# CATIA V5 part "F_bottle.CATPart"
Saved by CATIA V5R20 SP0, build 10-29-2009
Part number: Part1
Material "DS star": density 1000 kg/m3
Bounding box of the stored display mesh (mm): x -47.5 to 47.5, y -47.5 to 47.5, z -150 to 95
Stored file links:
  C:\Users\Lenovo\Desktop\我所做的源文件catia\bottle.CATPart
  D:\CATIAR20\win_b64\startup\materials\Catalog.CATMaterial
  D:\CATIAR20\win_b64\startup\materials\DS_star.jpg
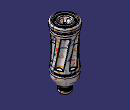
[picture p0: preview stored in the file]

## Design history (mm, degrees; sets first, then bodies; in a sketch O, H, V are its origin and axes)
Body1 (main body), material "DS star"
  Sketch1 on yz-plane, origin (0, 0, 0), H (0, 1, 0), V (0, 0, 1)
    point P1 (0, 70)
    line L1 (0, 70) -> (45, 70)
    line L2 (45, -70) -> (0, -70)
    line L3 (0, -70) -> (0, 70)
    point P2 (45, 70)
    point P3 (45, -70)
    arc A1 centre (532.5, 0) radius 492.5 from (45, 70) to (45, -70) ccw
    point P5 (532.5, 0)
    length L1 = 45
    distance P2 P3 = 140
    distance A1 L3 = 40
    coincidence: P1 V, P5 H
    horizontal: L1 H, L2 H
    vertical: L3 V
    symmetry: L1 L2 H
  Shaft1: profile Sketch1, axis Z axis, angle 360
  Sketch2 on face of Shaft1 from Sketch1.L1, origin (0, 0, 70), H (1, 0, 0), V (0, 1, 0)
    circle A1 centre (0, 0) radius 40
    radius A1 = 40
  Pad1: profile Sketch2, direction (0, 0, 1), length 5
  Sketch3 on end face of Pad1, origin (0, 0, 75), H (1, 0, 0), V (0, 1, 0)
    circle A1 centre (0, 0) radius 47.5
    radius A1 = 47.5
  Pad2: profile Sketch3, direction (0, 0, 1), length 20
  Fillet1: radius 4, on edge [face of Shaft1 from Sketch1.A1 | face of Shaft1 from Sketch1.L1]
  Fillet2: radius 6, on end face of Pad2; face of Pad2 from Sketch3.A1
  Fillet3: radius 2, on edge [face of Pad1 from Sketch2.A1 | start face of Pad2]; edge [face of Shaft1 from Sketch1.L1 | face of Pad1 from Sketch2.A1]
  Sketch4 on face of Shaft1 from Sketch1.L2, origin (0, 0, -70), H (1, 0, 0), V (0, -1, 0)
    circle A1 centre (0, 0) radius 40
    radius A1 = 40
  Pad3: profile Sketch4, direction (0, 0, -1), length 5
  Sketch5 on yz-plane, origin (0, 0, 0), H (0, 1, 0), V (0, 0, 1)
    line L1 (0, -75) -> (0, -125)
    line L2 (0, -125) -> (-20, -125)
    line L3 (-45, -75) -> (0, -75)
    reference projected line E1 (40, -75) -> (-40, -75) from edge [face of Pad3 from Sketch4.A1 | end face of Pad3]
    arc A1 centre (16.4164, -75.5418) radius 61.4188 from (-45, -75) to (-20, -125) ccw
    length L2 = 20
    length L1 = 50
    length L3 = 45
    vertical: L1 V
    horizontal: L2 H, L3 H
    coincidence: L3 E1, L1 V
  Shaft2: profile Sketch5, axis Z axis, angle 360
  Fillet4: radius 4, on edge [face of Shaft2 from Sketch5.A1 | face of Shaft2 from Sketch5.L3]; edge [face of Shaft1 from Sketch1.L2 | face of Shaft1 from Sketch1.A1]
  Fillet5: radius 2, on face of Pad3 from Sketch4.A1
  Sketch6 on face of Shaft2 from Sketch5.L2, origin (0, 0, -125), H (1, 0, 0), V (0, -1, 0)
    circle A1 centre (0, 0) radius 20
    reference projected circle E1 centre (0, 0) radius 20 from edge [face of Shaft2 from Sketch5.L2 | face of Shaft2 from Sketch5.A1]
    coincidence: E1 A1
  Pad4: profile Sketch6, direction (0, 0, -1), length 25
  Fillet6: radius 8, on edge [face of Pad4 from Sketch6.A1 | face of Shaft2 from Sketch5.A1]
  Extract1: ExtractElem face of Shaft1 from Sketch1.A1
  Plane1: type Offset, RefPlane zx-plane, Offset 50
  Sketch7 on Plane1, origin (0, 50, 0), H (-1, 0, 0), V (0, 0, 1)
    line L1 (0, 55.4683) -> (-19.5611, -55.4683)
    point P1 (0, 55.4683)
    point P2 (-19.5611, -55.4683)
    reference projected line E1 (-44.3708, -65.4683) -> (44.3708, -65.4683) from edge [face of Fillet4 | face of Shaft1 from Sketch1.A1]
    reference projected line E2 (-44.3708, 65.4683) -> (44.3708, 65.4683) from edge [face of Shaft1 from Sketch1.A1 | face of Fillet1]
    distance P2 E1 = 10
    distance P1 E2 = 10
    angle L1 V = 10
    coincidence: P1 V
  Project1: ToProject Sketch7, Support Extract1, Direction (0, 1, 0)
  Sketch8 on Plane1, origin (0, 50, 0), H (-1, 0, 0), V (0, 0, 1)
    line L1 (25.3857, 55.4683) -> (5.8246, -55.4683)
    point P1 (25.3857, 55.4683)
    point P2 (5.8246, -55.4683)
    reference projected line E1 (0, 55.4683) -> (-19.5611, -55.4683) from edge of Project1
    reference projected line E2 (-44.3708, -65.4683) -> (44.3708, -65.4683) from edge [face of Fillet4 | face of Shaft1 from Sketch1.A1]
    reference projected line E3 (-44.3708, 65.4683) -> (44.3708, 65.4683) from edge of Extract1
    reference projected line E4 (0, 55.4683) -> (-19.5611, -55.4683) from edge of Project1
    distance P2 E2 = 10
    distance E3 P1 = 10
    distance E4 L1 = 25
    parallelism: L1 E1
  Project2: ToProject Sketch8, Support Extract1, Direction (0, 1, 0)
  Line1: type PtPt, FirstPoint vertex of Project1, SecondPoint vertex of Project2
  Plane2: type Angle, RefPlane xy-plane, Direction Line1, Angle -30
  Circle1: stored without definition
  Circle2: stored without definition
  Loft1: Sections (Circle2; Circle1), Guides (Project1; Project2)
  Circle3: stored without definition
  DatumCurve1
  DatumCurve2
  Join1: Elements (DatumCurve1; DatumCurve2)
  Join2: Elements (Join1; Circle3)
  Fill1: Boundary Join2
  DatumCurve3
  Circle4: stored without definition
  Join3: Elements (DatumCurve3; Circle4)
  Fill2: Boundary Join3
  Join4: Elements (Fill2; Loft1; Fill1)
  Split1: SplitPlane Join4
  CircPattern1: of Join4, instances 6, angular step 60, axis from Z axis
  Split2: SplitPlane CircPattern1
  Fillet7: radius 2, on edge [face of Shaft1 from Sketch1.A1 | face of Split2] (x2); edge [face of Split2 | face of Shaft1 from Sketch1.A1] (x2)
  Fillet8: radius 2, on edge [face of Split2 | face of Split2]
  Fillet9: radius 2, on edge [face of Split2 | face of Split2]
  Fillet10: radius 2, on face of Split2
  Fillet11: radius 2, on face of Split2 (x3); face of Split1
  Fillet12: radius 2, on edge [face of Split2 | face of Shaft1 from Sketch1.A1] (x4); edge [face of Split1 | face of Shaft1 from Sketch1.A1]
  Fillet13: radius 2, on edge [face of Shaft1 from Sketch1.A1 | face of Split2] (x4); edge [face of Shaft1 from Sketch1.A1 | face of Split1]
  Sketch9 on end face of Pad2, origin (0, 0, 95), H (1, 0, 0), V (0, 1, 0)
    circle A1 centre (0, 0) radius 35
    circle A2 centre (0, 0) radius 30
    radius A2 = 30
    radius A1 = 35
  Pocket1: profile Sketch9, direction (0, 0, -1), length 4
  Fillet14: radius 3, on edge [face of Pocket1 from Sketch9.A2 | end face of Pad2]; edge [end face of Pad2 | face of Pocket1 from Sketch9.A1]
  Fillet15: radius 2, on edge [end face of Pocket1 | face of Pocket1 from Sketch9.A2]; edge [face of Pocket1 from Sketch9.A1 | end face of Pocket1]
  Sketch10 on yz-plane, origin (0, 0, 0), H (0, 1, 0), V (0, 0, 1)
    line L1 (0, 95) -> (23, 95)
    arc A1 centre (-4.9543, 102.7172) radius 29 from (23, 95) to (9.5635, 77.6127) cw
    arc A2 centre (6.1778, 78.5) radius 3.5 from (9.5635, 77.6127) to (2.992, 77.0506) cw
    arc A3 centre (-1.5591, 74.98) radius 5 from (2.992, 77.0506) to (0, 79.7307) ccw
    line L2 (0, 79.7307) -> (0, 95)
    length L1 = 23
    radius A1 = 29
    radius A3 = 5
    radius A2 = 3.5
    distance A2 L1 = 20
    tangency: A3 A2
    perpendicularity: L2 L1
    coincidence: L2 V
  Groove1: profile Sketch10, axis Sketch10.L2, angle 360
  Fillet16: radius 4, on edge [face of Groove1 from Sketch10.A1 | end face of Pad2]
  Extract2: ExtractElem face of Groove1 from Sketch10.A2
  Extract3: ExtractElem face of Groove1 from Sketch10.A1
  Sketch11 on end face of Pad2, origin (0, 0, 95), H (1, 0, 0), V (0, 1, 0)
    point P1 (17.3471, 9)
    line L1 (17.3471, 9) -> (8.6868, 4)
    point P2 (8.6868, 4)
    point P3 (8.6868, -4)
    point P4 (17.3471, -9)
    line L2 (17.3471, -9) -> (8.6868, -4)
    arc A1 centre (-0.5135, 0) radius 20 from (17.3471, 9) to (17.3471, -9) cw
    point P6 (22.2882, 0)
    reference projected circle E1 centre (0, 0) radius 9.5635 from edge [face of Groove1 from Sketch10.A1 | face of Groove1 from Sketch10.A2]
    angle H L1 = 30
    length L1 = 10
    distance P2 H = 4
    radius A1 = 20
    symmetry: P2 P3 H, P1 P4 H, L1 L2 H
    coincidence: P6 H, P3 E1
  Project3: ToProject Sketch11, Support Extract3, Direction (0, 0, 1)
  Sketch12 on yz-plane, origin (0, 0, 0), H (0, 1, 0), V (0, 0, 1)
    arc A1 centre (0, 80.6127) radius 5 from (-4, 77.6127) to (4, 77.6127) ccw
    point P2 (-4, 77.6127)
    point P3 (4, 77.6127)
    reference projected point E1 (-4, 77.6127) from vertex of Project3
    reference projected point E2 (4, 77.6127) from vertex of Project3
    reference projected point E3 (-4, 77.6127) from vertex of Project3
    radius A1 = 5
    coincidence: P2 E1, P3 E2, P2 E3
  Project4: ToProject Sketch12, Support Extract2, Direction (1, 0, 0)
  Extract4: ExtractElem edge of Project4
  Fill3: Boundary (Project3; Extract4)
  Split3: SplitPlane Fill3
  CircPattern2: of Fill3, instances 4, angular step 90, axis from Z axis
  Split4: SplitPlane CircPattern2
  Fillet17: radius 4, on edge [face of Groove1 from Sketch10.A2 | face of Groove1 from Sketch10.A1] (x4); edge [face of Groove1 from Sketch10.A2 | face of Split4] (x3); edge [face of Groove1 from Sketch10.A2 | face of Split3]
  Shell1: IntOffset 1, Face end face of Pad4, ExtOffset 0
  Intersect1: ToIntersect1 zx-plane, ToIntersect2 edge [face of Fillet6 | face of Pad4 from Sketch6.A1]
  Intersect2: ToIntersect1 zx-plane, ToIntersect2 edge [face of Fillet6 | face of Pad4 from Sketch6.A1]
  Extract5: ExtractElem vertex of Intersect2
  Point1: type OnSurface, Support face of Pad4 from Sketch6.A1, RefPoint Extract5, Length 3, Direction (-0.8377, -0.4801, -0.2603)
  Sketch13 on zx-plane, origin (0, 0, 0), H (-1, 0, 0), V (0, 0, 1)
    point P1 (20, -130.6653)
    arc A1 centre (18, -133.5376) radius 3.5 from (20, -130.6653) to (21.5, -133.5376) cw
    point P2 (18, -133.5376)
    line L1 (21.5, -133.5376) -> (21.5, -139.793)
    arc A2 centre (18, -139.793) radius 3.5 from (21.5, -139.793) to (20, -142.6653) cw
    point P5 (18, -139.793)
    point P6 (20, -142.6653)
    radius A1 = 3.5
    distance P2 V = 18
    distance P5 V = 18
    distance P6 V = 20
    distance P1 V = 20
    distance P6 P1 = 12
    vertical: L1 V
    tangency: A1 L1, A2 L1
  Point2: (0, 0, 0), relative to Sketch13.P1
  Helix1: Direction Z axis, RefPoint Point2, Pitch 5, Height 15, TaperAngle 0, RadiusLaw Sketch13
  Sketch14 on zx-plane, origin (0, 0, 0), H (0, 0, 1), V (1, 0, 0)
    line L1 (-128.6332, -17) -> (-130.3653, -20)
    line L2 (-130.3653, -20) -> (-130.9653, -20)
    point P3 (-130.9653, -20)
    line L3 (-130.9653, -20) -> (-132.6973, -17)
    line L4 (-132.6973, -17) -> (-128.6332, -17)
    reference projected point E1 (-130.6653, -20) from Point2
    reference projected point E2 (-130.6653, -20) from vertex of Helix1
    angle L4 L3 = 120
    angle L1 L4 = 120
    distance L2 L4 = 3
    distance E1 P3 H = 0.3
    length L2 = 0.6
    horizontal: L2 H, L4 H
    coincidence: E2 L2
  Rib1: profile Sketch14, centre curve Helix1
  Sketch15 on end face of Pad4, origin (0, 0, -150), H (1, 0, 0), V (0, -1, 0)
    projected circle E1 centre (0, 0) radius 19 from edge [end face of Pad4 | face of Shell1]
  Pocket2: profile Sketch15, direction (0, 0, 1), length 26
